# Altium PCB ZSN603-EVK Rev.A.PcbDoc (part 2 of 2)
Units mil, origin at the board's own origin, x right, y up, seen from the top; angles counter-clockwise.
Board outline 3937.01 x 3149.67 mil, 2 copper layers (Top Layer, Bottom Layer); 139 components, 76 nets, 380 pads, 360 vias.
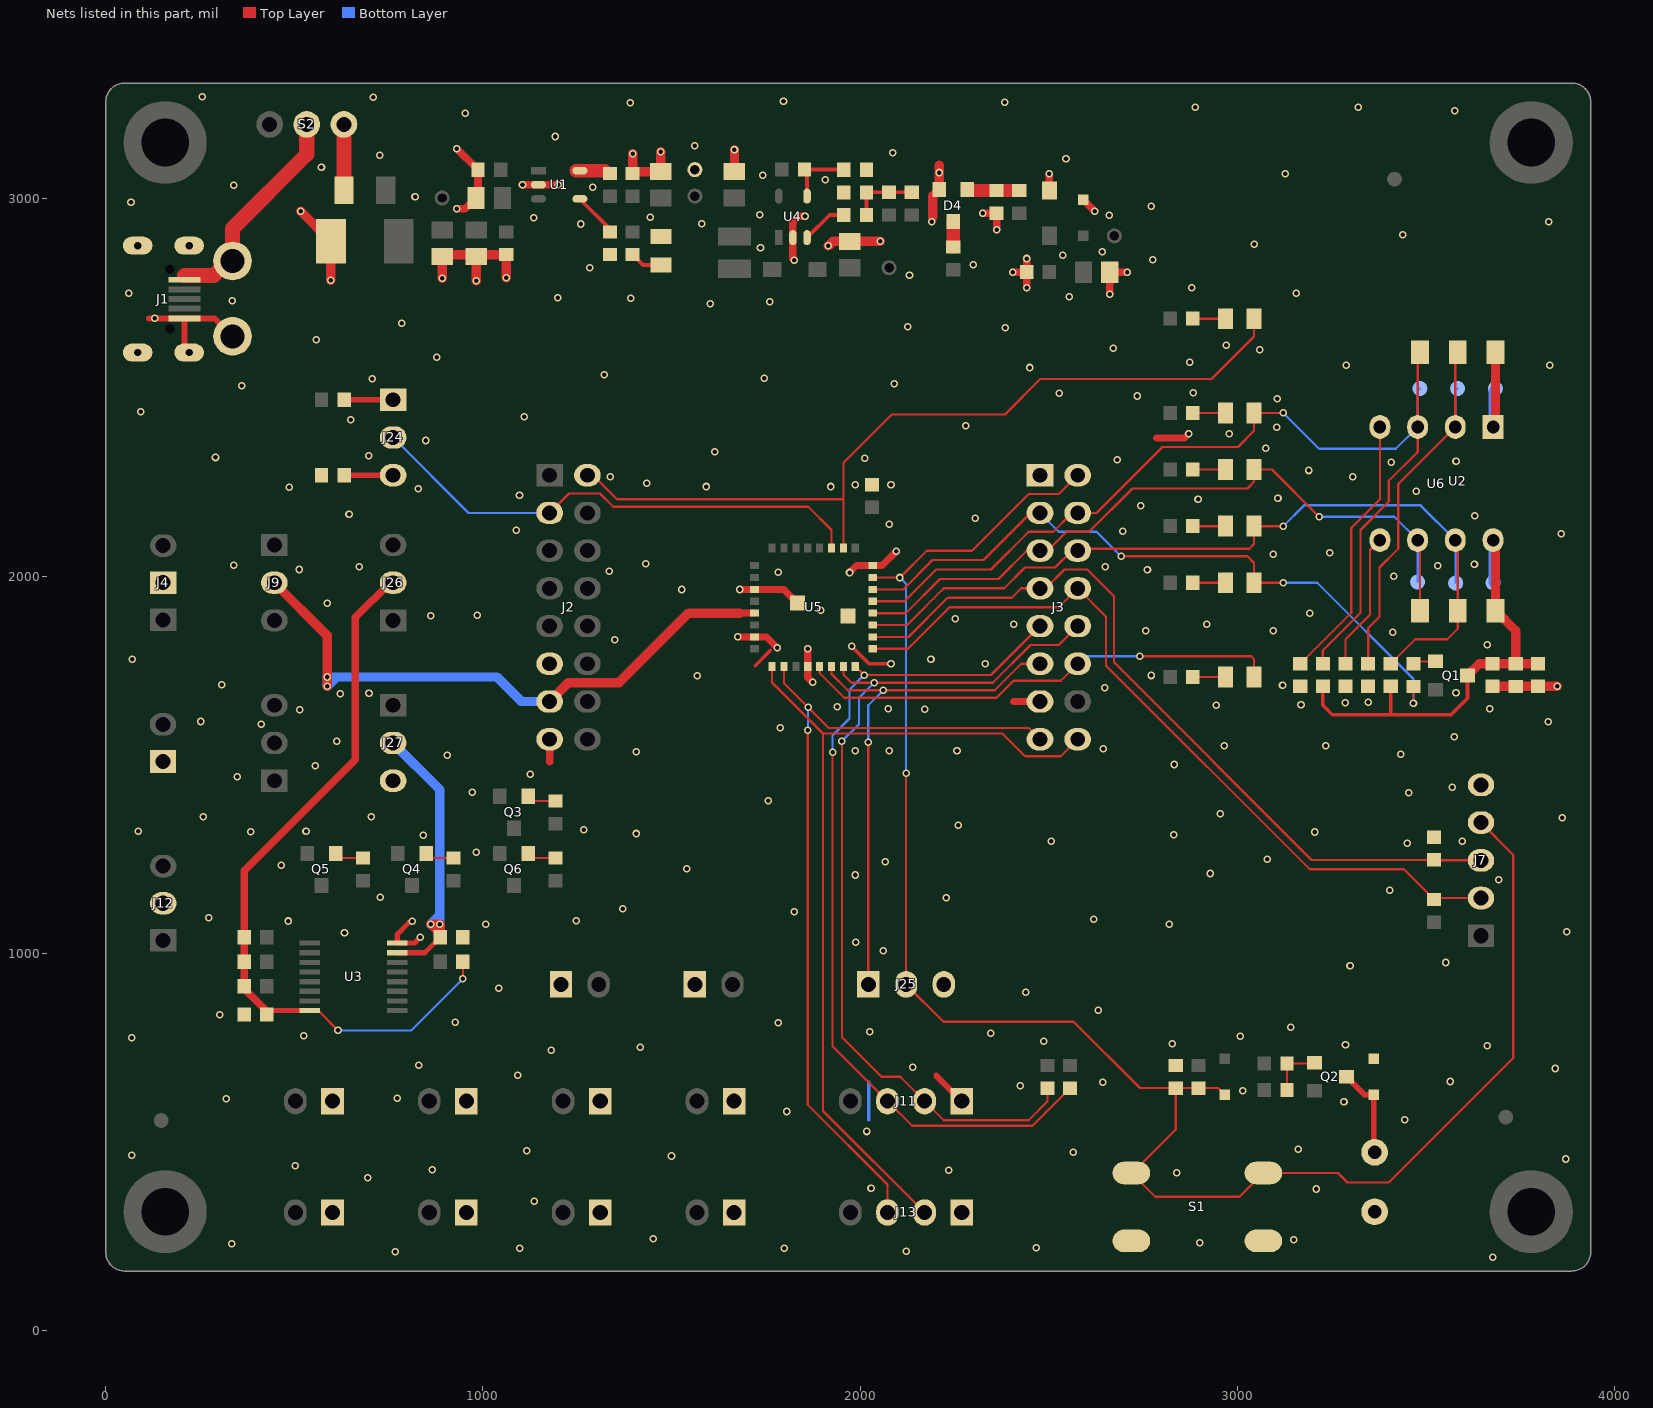
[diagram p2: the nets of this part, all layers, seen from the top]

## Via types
v1: diameter 20, hole 12, Top Layer to Bottom Layer, tented both sides, 360 vias

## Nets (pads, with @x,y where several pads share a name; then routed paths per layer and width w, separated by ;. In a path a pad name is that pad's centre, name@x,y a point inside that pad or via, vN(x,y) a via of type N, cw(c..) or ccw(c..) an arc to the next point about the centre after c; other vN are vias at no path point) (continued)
GND: BZ1.2 C1.2 C2.2 C3.2 C4.2 C5.2 C6.2 C7.2 C8.2 C9.2 C11.2 C12.2 C14.2 C15.1 C16.2 C17.2 C18.2 C19.2 C36.2 D2.1 D4.2 D5.2 D6.1 D7.2 J1.5 J1.6 J1.7 J1.8 J1.9 J2.11 J2.15 J3.1 J3.13 J4.2 J5.1 J6.1 J7.5 J10.1 J11.1 J12.2 J13.1 J14.1 J15.1 J16.1 J17.1 J18.1 J19.1 J20.1 J21.1 J22.1 J23.2 J25.3 J27.3 LED1.2 R5.1 R8.2 R24.1 R25.1 R27.1 R30.1 R31.1 R32.1 R38.1 S1.2 S1.3 T3.1 T5.1 U1.2 U2.6 U3.8 U4.2 U5.4 U5.16 U5.27 U5.31 U5.33 U5.34 U6.1 | length 4007.3
  Top Layer w10: 1721.97,1762.48 1761.97,1802.48 ; v1(1977.97,1813.48) 2023.97,1767.48 v1(2081.97,1767.48)
  Top Layer w13.78: 803.47,1080.98 773.11,1050.62 U3.8@773.11,1027.05 818.54,1027.05 v1(833.97,1042.48)
  Top Layer w15.75: 115.09,2683.36 J1.5@209.02,2683.36 ; J1.7@221.22,2592.81 209.02,2605.02 J1.5@209.02,2683.36 ; J23.2@336.16,2635.54 288.34,2683.36 J1.5@209.02,2683.36 ; 2201.97,675.43 J11.1@2269.61,607.8
  Top Layer w19: v1(1676.23,1838.74) U5.31@1720.28,1838.74 1751.71,1838.74 v1(1780.97,1809.48) ; v1(1680.97,1964.48) 1681.22,1964.72 U5.27@1720.28,1964.72 1797.45,1964.72 U5.33@1833.67,1928.5 ; v1(1861.23,1807.73) U5.4@1861.23,1760.79 1861.23,1731.23 v1(1873.97,1718.48) ; v1(1971.97,2009.48) 1990.21,2027.72 U5.16@2033.67,2027.72 2058.21,2027.72 v1(2095.97,2065.48) ; 2406.97,1667.48 J3.13@2476.97,1667.48 ; 2786.47,2366.48 2859.97,2366.48 v1(2870.97,2377.48)
  Top Layer w20: v1(930.97,2973.48) 952.97,2973.48 C1.2@981.97,3002.48 986.97,3007.48 C2.2@986.97,3077.48 v1(930.97,3133.48) ; v1(1104.97,3037.48) U1.2@1146.97,3037.48 v1(1199.97,3037.48) ; 1176.97,1507.48 J2.15@1176.97,1567.48 ; v1(1825.97,2837.48) 1821.97,2841.48 U4.2@1821.97,2897.48 1821.97,2937.48 1837.97,2953.48 v1(1853.97,2953.48) ; v1(2325.48,2962.48) C15.1@2361.97,2962.48 v1(2361.97,2917.97) ; v1(2405,2806) R27.1@2442,2806 ; v1(2442,2765) R27.1@2442,2806 ; v1(2442,2842) R27.1@2442,2806 ; D5.2@2501.97,3022.48 v1(2501.97,3066.97) ; D7.2@2591.97,2997.48 v1(2621.97,2967.48) ; v1(2662,2747) C14.2@2662,2806 v1(2708,2806)
  Top Layer w25: v1(516.97,2967.48) D6.1@596.97,2887.48 v1(596.97,2784.48) ; v1(891.97,2789.48) C16.2@891.97,2847.48 896.97,2852.48 C18.2@1061.97,2852.48 v1(1061.97,2791.48) ; v1(981.97,2782.48) C17.2@981.97,2847.48 ; v1(1396.97,3119.48) C5.2@1396.97,3067.48 1401.97,3072.48 C4.2@1471.97,3072.48 v1(1471.97,3125.48) ; C12.2@1666.97,3072.48 v1(1666.97,3130.48) ; v1(1915.97,2875.48) 1927.97,2887.48 C11.2@1971.97,2887.48 v1(2053.97,2887.48) ; 2192.97,2951.48 2192.97,3008.38 D4.2@2209.57,3024.98 2209.57,3089.08 ; R8.2@3676.97,1707.48 C36.2@3796.97,1707.48 v1(3847.97,1707.48) ; U6.1@3678.24,2395.4 3684.78,2401.94 U2.6@3684.78,2593.45
  Bottom Layer w10: 2023.07,558.58 2023.07,657.48
  Bottom Layer w25: U6.1@3678.24,2395.4 3678.24,2491.4 T5.1@3684.24,2497.4
  other v1: 3677,194 766.97,208.48 2122.97,209.48 1097.97,217.48 1798.97,217.48 2466.97,219.48 333.97,229.48 2899.97,232.48 3150,240 1451.97,242.48 1135.97,342.48 3210,375 2028.97,377.48 694.97,404.48 2838.97,417.48 2234.97,424.48 865.97,426.48 502.97,436.48 3870.97,454.48 1499.97,462.48 68.97,464.48 2564.97,472.48 1115.97,476.48 3161.97,480.48 2017.97,527.48 3443.97,558.48 1804.97,580.48 3282.97,606.48 318.97,614.48 772.97,615.48 3015,635 2424.97,648.48 2642.97,658.48 3565,660 1091.97,676.48 3842.97,694.48 2139.97,697.48 829.97,703.48 1180.97,742.48 1416.97,750.48 3662.97,754.48 3286.97,757.48 2827.97,760.48 2486.97,766.48 68.97,776.48 3007.97,779.48 524.97,781.48 2346.97,788.48 2025.97,792.48 3141.97,803.48 1782.97,815.48 926.97,816.48 301.97,836.48 2631.97,849.48 2438.97,896.48 1041.97,907.48 3298.97,966.48 3552.97,975.48 2061.97,1006.48 1987.97,1029.48 632.97,1054.48 3873.97,1056.48 1006.97,1077.48 2819.97,1077.48 812.97,1084.48 483.97,1085.48 1246.97,1086.48 2620,1090 272.97,1094.48 1825.97,1109.48 1370.97,1118.48 2228.97,1147.48 727.97,1148.48 3403.97,1167.48 3692.97,1194.48 1986.97,1207.48 2927.97,1211.48 1540.97,1224.48 464.97,1233.48 2066.97,1242.48 3079.97,1249.48 981.97,1267.48 3450.97,1291.48 2506.97,1297.48 3595.97,1297.48 841.97,1312.48 2831.97,1314.48 1406.97,1317.48 3205.97,1321.48 383.97,1322.48 85.97,1323.48 530.97,1323.48 1266.97,1327.48 2260,1340 3861.97,1359.48 257.97,1361.48 703.97,1361.48 2955,1370 1756.97,1404.48 3455,1425 971.97,1427.48 3570,1440 348.97,1467.48 1125,1475 555.97,1497.48 2832.97,1500.48 905.97,1524.48 3433.97,1527.48 1406.97,1534.48 1986.97,1537.48 2076.97,1537.48 2256.97,1537.48 2644.97,1542.48 2965,1550 3235,1550 611.97,1562.48 3574.97,1574.48 1787.97,1598.48 411.97,1607.48 3824.97,1613.48 251.97,1614.48 513.97,1645.48 2171.97,1647.48 2074.97,1648.48 3668.97,1648.48 1939.97,1653.48 2943.97,1657.48 3168.97,1658.48 3285.97,1664.48 3346.97,1665.48 621.97,1687.48 697.97,1689.48 3579.97,1690.48 2648.97,1703.48 3120,1710 306.97,1712.48 1567.97,1735.48 2771.97,1736.48 2331.97,1767.48 69.97,1779.48 2187.97,1779.48 3662.97,1818.48 1349.97,1831.48 3411.97,1851.48 2757.97,1855.48 3095,1855 2406.97,1872.48 2918.97,1872.48 2251.97,1887.48 861.97,1894.48 984.97,1896.48 3191.97,1901.48 1895.97,1909.48 586.97,1927.48 1526.97,1964.48 3414.97,1999.48 1782.97,2010.48 1334.97,2012.48 2761.97,2016.48 512.97,2017.48 671.97,2024.48 2649.97,2024.48 3530.97,2027.48 339.97,2028.48 3628.97,2031.48 1431.97,2032.48 3094.97,2058.48 3244.97,2062.48 3858.97,2112.48 2696.97,2119.48 1088.97,2121.48 2076.97,2137.48 2304.97,2153.48 3630,2160 644.97,2163.48 2743.97,2186.48 2895.97,2203.48 3107.97,2206.48 1096.97,2214.48 3475,2225 827.97,2231.48 485.97,2235.48 1591.97,2237.48 1921.97,2237.48 1986.97,2242.48 2081.97,2242.48 1434.97,2246.48 1337.97,2263.48 3305.97,2263.48 3190,2280 3407.97,2301.48 3580,2305 2681.97,2308.48 2011.97,2312.48 290.97,2314.48 696.97,2318.48 1614.97,2329.48 3074.97,2338.48 848.97,2359.48 2978.97,2377.48 3105,2395 2279.97,2398.48 649.97,2414.48 1109.97,2422.48 92.97,2435.48 3105.97,2470.48 2734.97,2477.48 2527.97,2484.48 2882.97,2486.48 360,2505 2089.97,2510.48 706.97,2523.48 1745.97,2524.48 1321.97,2533.48 2450,2553 3288.97,2558.48 3827.97,2558.48 2873.97,2566.48 877.97,2580.48 3060,2600 2670.97,2604.48 2970.97,2612.48 557.97,2626.48 2385,2659 2126.97,2661.48 785,2670 130,2683.36 1602.97,2722.48 1760.97,2727.48 335,2730 1391.97,2736.48 1198.97,2738.48 2555,2741 60.97,2750.48 3156.97,2750.48 2879,2764 2131,2798 1282.97,2817.48 2300,2825 2776,2839 2537,2851 2642,2860 1735.97,2870.48 3045,2880 3438.97,2904.48 1258.97,2933.48 1579.97,2934.48 3825.97,2939.48 2190,2940 1134.97,2950.48 1443.97,2951.48 2661,2957 1733.97,2958.48 2771.97,2980.48 66.97,2991.48 819.97,3005.48 1290.97,3030.48 338.97,3036.48 1907.97,3050.48 1741.97,3062.48 3126.97,3066.48 2209.57,3070 571.97,3084.48 2545.97,3106.48 725.97,3115.48 2086.97,3122.48 1561.97,3141.48 1191.97,3165.48 952.97,3227.48 3576.97,3233.48 2888.97,3242.48 3320.97,3242.48 1390.97,3254.48 2382.97,3256.48 1796.97,3258.48 708.97,3269.48 255.97,3270.48
NetBZ1_1: BZ1.1 D2.2 Q2.3 | length 246
  Top Layer w15: Q2.3@3289.47,672.48 3336.97,624.98 D2.2@3361.97,624.98 3361.97,474.4 BZ1.1@3364.24,472.14
NetC3_1: C3.1 U1.4 | length 120.7
  Top Layer w10: U1.4@1256.97,3000.08 1336.97,2920.08 C3.1@1336.97,2912.48
NetC10_2: C10.2 R21.1 R23.1 R25.2 | length 180
  Top Layer w10: R23.1@2016.97,2957.48 R25.2@2016.97,3017.48 R21.1@2076.97,3017.48 C10.2@2136.97,3017.48
NetC13_2: C13.2 D4.3 | length 67.5
  Top Layer w35: C13.2@2246.97,2872.48 D4.3@2246.97,2939.98
NetC15_2: C15.2 D4.1 R26.1 | length 138.6
  Top Layer w35: D4.1@2284.37,3024.98 2286.87,3022.48 C15.2@2361.97,3022.48 R26.1@2421.97,3022.48
NetF1_1: F1.1 S2.3 | length 170.3
  Top Layer w40: S2.3@631.39,3197.54 631.39,3027.94 F1.1@631.85,3027.48
NetJ1_1: J1.1 J23.1 S2.2 | length 587.1
  Top Layer w40: 208.32,2797.48 286.97,2797.48 325.04,2835.54 J23.1@336.16,2835.54 336.16,2921.67 532.96,3118.47 S2.2@532.96,3197.54
NetJ24_1: J24.1 R37.2 | length 130
  Top Layer w15: R37.2@631.97,2467.48 J24.1@761.97,2467.48
NetJ24_3: J24.3 R38.2 | length 130
  Top Layer w15: R38.2@631.97,2267.48 J24.3@761.97,2267.48
NetLED1_1: LED1.1 R2.2 | length 86.5
  Top Layer w10: R2.2@1396.97,2852.48 1424.65,2824.8 LED1.1@1471.97,2824.8
NetLED2_1: LED2.1 R12.2 | length 87.3
  Top Layer w6: R12.2@2881.97,1732.48 LED2.1@2969.3,1732.48
NetLED3_1: LED3.1 R33.1 | length 87.3
  Top Layer w6: R33.1@2881.97,1982.48 LED3.1@2969.3,1982.48
NetLED4_1: LED4.1 R34.1 | length 87.3
  Top Layer w6: R34.1@2881.97,2132.48 LED4.1@2969.3,2132.48
NetLED5_1: LED5.1 R35.1 | length 87.3
  Top Layer w6: R35.1@2881.97,2432.48 LED5.1@2969.3,2432.48
NetLED6_1: LED6.1 R36.1 | length 87.3
  Top Layer w6: R36.1@2881.97,2282.48 LED6.1@2969.3,2282.48
NetLED7_1: LED7.1 R39.1 | length 87.3
  Top Layer w6: R39.1@2881.97,2682.48 LED7.1@2969.3,2682.48
NetQ1_1: Q1.1 R9.2 | length 61.2
  Top Layer w6: R9.2@3467.24,1767.4 3473.64,1773.8 Q1.1@3525.74,1773.8
NetQ2_1: Q2.1 R10.1 R11.2 | length 143.5
  Top Layer w6: R10.1@3131.97,637.48 R11.2@3131.97,707.48 3202.07,707.48 Q2.1@3204.47,709.88
NetQ3_1: Q3.1 R15.1 | length 77.8
  Top Layer w6: Q3.1@1119.73,1416.33 1132.23,1403.83 R15.1@1192.33,1403.83
NetQ4_1: Q4.1 R16.1 | length 77.8
  Top Layer w6: Q4.1@849.37,1264.98 861.87,1252.48 R16.1@921.97,1252.48
NetQ5_1: Q5.1 R19.1 | length 77.8
  Top Layer w6: Q5.1@609.37,1264.98 621.87,1252.48 R19.1@681.97,1252.48
NetQ6_1: Q6.1 R20.1 | length 77.8
  Top Layer w6: Q6.1@1119.73,1264.98 1132.23,1252.48 R20.1@1192.33,1252.48
NetR1_1: R1.1 U1.5 | length 93.1
  Top Layer w35: U1.5@1246.97,3074.88 U1.5@1256.97,3074.88 1322.57,3074.88 1329.97,3067.48 R1.1@1336.97,3067.48
NetR22_1: R22.1 R24.2 U4.4 | length 178.1
  Top Layer w10: U4.4@1859.37,3007.48 1859.37,3071.04 R22.1@1852.44,3077.98 1956.48,3077.98 R24.2@1956.97,3077.48
NetR23_2: R23.2 U4.3 | length 122.5
  Top Layer w10: U4.3@1859.37,2897.48 1919.37,2957.48 R23.2@1956.97,2957.48
NetR30_2: R30.2 U6.4 | length 715.4
  Top Layer w6: R30.2@3166.97,1767.48 3301.97,1902.48 3301.97,2127.48 3378.24,2203.75 U6.4@3378.24,2395.4
NetR31_2: R31.2 U6.5 | length 365.7
  Top Layer w6: R31.2@3286.97,1767.48 3286.97,1832.48 3351.97,1897.48 3351.97,2069.13 U6.5@3378.24,2095.4
NRST: C6.1 D1.1 J3.2 J7.4 J25.2 R4.1 S1.1 S1.4 U5.15 | length 4854.1
  Top Layer w6: U5.15@2033.67,1996.22 v1(2105.71,1996.22) 2176.97,2067.48 2296.97,2067.48 2446.97,2217.48 2526.97,2217.48 J3.2@2576.97,2267.48 ; v1(2121.97,1477.48) J25.2@2121.97,917.48 2220.97,818.48 2565.97,818.48 2741.97,642.48 C6.1@2836.97,642.48 ; D1.1@2966.97,624.98 2949.47,642.48 R4.1@2896.97,642.48 C6.1@2836.97,642.48 ; J7.4@3646.24,1346.4 3731.97,1260.66 3731.97,722.48 3401.97,392.48 3291.97,392.48 3267.06,417.4 S1.4@3069.24,417.4 3006.18,354.33 2782.3,354.33 S1.1@2719.24,417.4 2721.89,417.4 2836.97,532.48 C6.1@2836.97,642.48
  Bottom Layer w6: v1(2105.71,1996.22) 2121.97,1979.96 v1(2121.97,1477.48)
PA2/NC: J2.2 LED7.2 U5.18 | length 2206.1
  Top Layer w6: J2.2@1276.97,2267.48 1291.97,2267.48 1355.62,2203.83 1955.71,2203.83 ; U5.18@1955.71,2074.17 1955.71,2203.83 ; LED7.2@3044.65,2682.48 3044.65,2635.16 2931.97,2522.48 2477.97,2522.48 2383.97,2428.48 2083.97,2428.48 1955.71,2300.22 1955.71,2203.83
PA3/MODE_DET: J2.3 J24.2 U5.19 | length 1354.3
  Top Layer w6: J2.3@1176.97,2167.48 1228.33,2218.83 1310.62,2218.83 1345.62,2183.83 1862.33,2183.83 1924.22,2121.94 U5.19@1924.22,2074.17
  Bottom Layer w6: J24.2@761.97,2367.48 961.97,2167.48 J2.3@1176.97,2167.48
PA9/UART1_TX: J3.15 J13.3 U5.2 | length 2212.8
  Top Layer w6: U5.2@1798.23,1760.79 1798.23,1716.22 v1(1861.97,1652.48) 1916.97,1597.48 2446.97,1597.48 J3.15@2476.97,1567.48 ; v1(1860.93,1591.44) 1860.93,598.52 2072.76,386.69 J13.3@2072.76,312.8
  Bottom Layer w6: v1(1860.93,1591.44) 1861.97,1592.48 v1(1861.97,1652.48)
PA10/UART1_RX: J3.16 J13.2 U5.1 | length 2334
  Top Layer w6: U5.1@1766.74,1760.79 1766.74,1717.72 1901.97,1582.48 ; J13.2@2171.18,312.8 1901.97,582.01 1901.97,1582.48 ; J3.16@2576.97,1567.48 2531.97,1522.48 2436.97,1522.48 2376.97,1582.48 1901.97,1582.48
PA12/LED: J3.12 LED2.2 U5.5 | length 1293.1
  Top Layer w6: U5.5@1892.72,1760.79 1892.72,1742.73 1957.97,1677.48 2361.97,1677.48 2406.97,1722.48 2531.97,1722.48 J3.12@2576.97,1767.48 ; v1(2741.97,1787.48) 3036.97,1787.48 3044.65,1779.8 LED2.2@3044.65,1732.48
  Bottom Layer w6: J3.12@2576.97,1767.48 2596.97,1787.48 v1(2741.97,1787.48)
PA13/SWDIO/BOOT0: J3.8 J7.2 R3.1 U5.9 | length 2098.4
  Top Layer w6: U5.9@2033.67,1807.24 2126.74,1807.24 2236.97,1917.48 2526.97,1917.48 J3.8@2576.97,1967.48 2651.97,1892.48 2651.97,1762.48 3191.97,1222.48 3441.97,1222.48 R3.1@3521.97,1142.48 3525.89,1146.4 J7.2@3646.24,1146.4
PA14/SWCLK/BOOT1: J3.7 J7.3 R5.2 U5.10 | length 2108.5
  Top Layer w6: U5.10@2033.67,1838.74 2128.23,1838.74 2231.97,1942.48 2401.97,1942.48 2426.97,1967.48 J3.7@2476.97,1967.48 2491.97,1967.48 2541.97,2017.48 2601.97,2017.48 2673.19,1946.27 2673.19,1771.27 3196.97,1247.48 R5.2@3521.97,1247.48 3523.06,1246.4 J7.3@3646.24,1246.4
PA15/INT: J3.11 J25.1 U5.6 | length 1416.6
  Top Layer w6: U5.6@1924.22,1760.79 1924.22,1740.24 1966.97,1697.48 v1(2061.97,1697.48) 2356.97,1697.48 2426.97,1767.48 J3.11@2476.97,1767.48 ; J25.1@2021.97,917.48 v1(2021.97,1559.98)
  Bottom Layer w6: v1(2021.97,1559.98) 2021.97,1657.48 v1(2061.97,1697.48)
PB3/SAM_RST: J3.6 LED4.2 R28.1 T6.1 U2.2 U5.11 U6.7 | length 2310.3
  Top Layer w6: U5.11@2033.67,1870.24 2124.73,1870.24 2221.97,1967.48 2381.97,1967.48 2436.97,2022.48 2516.97,2022.48 2561.97,2067.48 J3.6@2576.97,2067.48 2581.97,2072.48 3031.97,2072.48 3044.65,2085.16 LED4.2@3044.65,2132.48 v1(3121.97,2132.48) ; R28.1@3406.97,1767.48 3471.97,1832.48 3556.97,1832.48 3584.78,1860.29 U2.2@3584.78,1908.41 3584.78,2088.85 U6.7@3578.24,2095.4
  Bottom Layer w6: v1(3121.97,2132.48) 3176.97,2187.48 3486.16,2187.48 U6.7@3578.24,2095.4 3579.24,2094.4 T6.1@3579.24,1981.4
PB4/SAM_CLK: J3.5 LED6.2 T7.1 U2.3 U5.12 U6.6 | length 1999.4
  Top Layer w6: U5.12@2033.67,1901.73 2121.22,1901.73 2211.97,1992.48 2366.97,1992.48 2441.97,2067.48 J3.5@2476.97,2067.48 2496.97,2067.48 2546.97,2117.48 2606.97,2117.48 2721.97,2232.48 3026.97,2232.48 3044.65,2250.16 LED6.2@3044.65,2282.48 3091.97,2282.48 v1(3216.97,2157.48) ; U6.6@3478.24,2095.4 3484.78,2088.85 U2.3@3484.78,1908.41
  Bottom Layer w6: v1(3216.97,2157.48) 3416.16,2157.48 U6.6@3478.24,2095.4 T7.1@3478.24,1984.4
PB5/SAM_IO: J3.4 LED5.2 R29.1 T8.1 U2.4 U5.13 U6.3 | length 2779.7
  Top Layer w6: U5.13@2033.67,1933.23 2117.72,1933.23 2201.97,2017.48 2346.97,2017.48 2446.97,2117.48 2511.97,2117.48 2561.97,2167.48 J3.4@2576.97,2167.48 2626.97,2167.48 2801.97,2342.48 3001.97,2342.48 3044.65,2385.16 LED5.2@3044.65,2432.48 v1(3121.97,2432.48) ; R29.1@3226.97,1767.48 3226.97,1802.48 3326.97,1902.48 3326.97,2122.48 3401.97,2197.48 3401.97,2252.48 3478.24,2328.75 U6.3@3478.24,2395.4 3478.24,2586.91 U2.4@3484.78,2593.45
  Bottom Layer w6: v1(3121.97,2432.48) 3216.97,2337.48 3420.33,2337.48 U6.3@3478.24,2395.4 3478.24,2491.4 T8.1@3484.24,2497.4
PB6/I2C_SCL: J3.9 J11.3 R7.1 U5.8 | length 2330.6
  Top Layer w6: v1(1926.97,1532.48) 1926.97,753.58 J11.3@2072.76,607.8 2138.07,542.48 2456.97,542.48 R7.1@2556.97,642.48 ; U5.8@1987.21,1760.79 v1(2010.52,1737.48) 2346.97,1737.48 J3.9@2476.97,1867.48
  Bottom Layer w6: v1(1926.97,1532.48) 1926.97,1577.48 1971.97,1622.48 1971.97,1698.94 v1(2010.52,1737.48)
PB7/I2C_SDA: J3.10 J11.2 R6.1 U5.7 | length 2381.3
  Top Layer w6: v1(1951.97,1562.48) 1951.97,777.48 2056.97,672.48 2106.5,672.48 J11.2@2171.18,607.8 2221.5,557.48 2446.97,557.48 2496.97,607.48 R6.1@2496.97,642.48 ; U5.7@1955.71,1760.79 1955.71,1738.74 1976.97,1717.48 v1(2036.97,1717.48) 2351.97,1717.48 2451.97,1817.48 2526.97,1817.48 J3.10@2576.97,1867.48
  Bottom Layer w6: v1(1951.97,1562.48) 1996.97,1607.48 1996.97,1677.48 v1(2036.97,1717.48)
PB8/SAM_NPWR: J3.3 LED3.2 R9.1 U5.14 | length 1839.7
  Top Layer w6: U5.14@2033.67,1964.72 2114.22,1964.72 2191.97,2042.48 2326.97,2042.48 2451.97,2167.48 J3.3@2476.97,2167.48 ; v1(2691.97,2052.48) 3026.97,2052.48 3044.65,2034.8 LED3.2@3044.65,1982.48 v1(3121.97,1982.48) ; v1(3467.24,1662.75) R9.1@3467.24,1707.4
  Bottom Layer w6: J3.3@2476.97,2167.48 2526.97,2117.48 2626.97,2117.48 v1(2691.97,2052.48) ; v1(3121.97,1982.48) 3211.97,1982.48 3467.24,1727.21 v1(3467.24,1662.75)
PVPP: R32.2 T11.1 U2.5 U6.2 | length 1029
  Top Layer w6: R32.2@3346.97,1767.48 3346.97,1862.48 3376.97,1892.48 3376.97,2022.48 3426.97,2072.48 3426.97,2244.13 U6.2@3578.24,2395.4 3578.24,2586.91 U2.5@3584.78,2593.45
  Bottom Layer w6: U6.2@3578.24,2395.4 3578.24,2491.4 T11.1@3584.24,2497.4
SAM_VCC: C7.1 C36.1 Q1.3 R8.1 R28.2 R29.2 T4.1 U2.1 U6.8 | length 1262.4
  Top Layer w10: R29.2@3226.97,1707.48 3226.97,1657.48 3251.97,1632.48 3406.97,1632.48 ; R28.2@3406.97,1707.48 3406.97,1632.48 ; Q1.3@3610.74,1736.4 3610.74,1676.25 3566.97,1632.48 3406.97,1632.48
  Top Layer w25: Q1.3@3610.74,1736.4 3641.83,1767.48 R8.1@3676.97,1767.48 C7.1@3738.24,1767.48 ; U6.8@3678.24,2095.4 3684.78,2088.85 U2.1@3684.78,1908.41 3738.24,1854.95 C7.1@3738.24,1767.48 ; C7.1@3738.24,1767.4 C7.1@3738.24,1767.48 ; C36.1@3796.97,1767.48 C7.1@3738.24,1767.48
  Bottom Layer w25: T4.1@3678.24,1982.4 U6.8@3678.24,2095.4
VCC_4051: C9.1 J26.2 R13.2 R14.2 R17.2 R18.2 U3.16 | length 1973.7
  Top Layer w6: U3.16@540.83,847.91 563.3,847.91 v1(615.74,795.48) ; v1(946.97,932.48) R18.2@946.97,977.48
  Top Layer w13.78: C9.1@432.97,847.91 U3.16@540.83,847.91
  Top Layer w20: C9.1@425.97,847.48 366.97,906.48 R14.2@366.97,912.48 R13.2@366.97,977.48 R17.2@366.97,1042.48 366.97,1218.48 661.97,1513.48 661.97,1890.48 753.97,1982.48 J26.2@761.97,1982.48 ; C9.1@426.97,837.48 C9.1@432.97,831.48
  Bottom Layer w6: v1(615.74,795.48) 809.97,795.48 v1(946.97,932.48)
VCC_ANT: J2.13 J9.2 U5.29 | length 1650.6
  Top Layer w19: 1681.22,1901.73 U5.29@1720.28,1901.73
  Top Layer w25: J9.2@446.97,1982.48 586.97,1842.48 v1(586.97,1732.48) v1(586.97,1707.48) ; J2.13@1176.97,1667.48 1226.97,1717.48 1360.97,1717.48 1545.23,1901.73 1681.22,1901.73
  Bottom Layer w25: J2.13@1176.97,1667.48 1101.97,1667.48 1036.97,1732.48 611.97,1732.48 ; 611.97,1732.48 v1(586.97,1732.48) v1(586.97,1707.48) 611.97,1732.48
VEE_4051: C8.1 J27.2 U3.7 | length 814.9
  Top Layer w13.78: U3.7@773.11,1001.46 845.95,1001.46 C8.1@886.97,1042.48
  Top Layer w25: C8.1@886.97,1042.48 C8.1@886.97,1052.48 ; C8.1@886.97,1052.48 886.97,1076.48 v1(885.97,1077.48) v1(861.97,1077.48) C8.1@886.97,1052.48
  Bottom Layer w25: J27.2@761.97,1557.48 885.97,1433.48 885.97,1101.48 ; 885.97,1101.48 v1(885.97,1077.48) v1(861.97,1077.48) 885.97,1101.48
pads on no net: HOLE1.1 HOLE2.1 HOLE3.1 HOLE4.1 J1.0 J1.2 J1.3 J1.4 MARK2.0 MARK3.0 MARK4.0 S2.1

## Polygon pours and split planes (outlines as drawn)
GND on Top Layer "GND_L01_P1002" (solid, remove dead copper, pour order 1002): -2.36,179.98 ccw(c47.64,179.98) 47.2,129.99 3884.61,129.99 3884.61,129.92 ccw(c3884.61,179.92) 3934.61,179.49 3934.61,3229.98 ccw(c3885.1,3229.98) 3885.53,3279.48 3885.53,3279.59 47.21,3279.59 47.6,3279.55 ccw(c47.6,3229.55) -2.4,3229.99
GND on Bottom Layer "GND_L02_P1003" (solid, remove dead copper, pour order 1003): 0,207.54 ccw(c50,207.54) 49.56,157.54 3886.97,157.54 3886.97,157.48 ccw(c3886.97,207.48) 3936.97,207.04 3936.97,3257.54 ccw(c3887.46,3257.54) 3887.89,3307.04 3887.89,3307.15 49.57,3307.15 49.96,3307.11 ccw(c49.96,3257.11) -0.04,3257.54

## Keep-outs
Keep-Out Layer:
  lines w5: -0.07,3257.45 cw(c49.57,3257.45) 49.14,3307.08 ; -0.04,207.04 -0.04,3257.45 ; 0,-65.55 0,0 ; 0,207.54 ccw(c50,207.54) 49.56,157.54 ; 49.46,157.54 3886.97,157.54 ; 49.57,3307.09 3887.89,3307.09 ; 3886.97,157.48 ccw(c3886.97,207.48) 3936.97,207.04 3936.97,3257.54 ccw(c3887.46,3257.54) 3887.89,3307.04 ; 3936.97,-65.55 3936.97,0 4002.52,0 ; 3936.97,3307.09 4002.52,3307.09

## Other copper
Top Layer:
  pour cut-out: 782.68,3073.9 638.39,3073.9 622.97,3058.48 622.97,3038.48 657.97,3003.48 750.26,3003.48 782.68,2971.06
  pour cut-out: 1773.93,2974.82 1855,2974.82 1855,2985 1773.93,2985
  pour cut-out: 3546.16,2639.95 3546.16,2625 3505,2625 3505,2639.95
  pour cut-out: 1178.75,1670 1278.75,1670 1278.75,1570 1171.25,1570

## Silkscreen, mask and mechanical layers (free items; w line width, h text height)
Top Overlay:
  region: 1908.57,106.48 1908.57,94.48 1763.57,94.48 1763.57,67.48 1908.57,67.48 1908.57,56.48 1970.57,81.48
  lines w7.87: 991.15,1627.48 991.15,1130.08 ; 991.15,1697.31 991.15,1836.48 ; 991.15,1907.48 991.15,2704.88 2762.8,2704.88 2762.8,2207.48 ; 1365.16,1497.48 1365.16,1228.5 2388.78,1228.5 2388.78,1497.48 ; 1365.16,2347.48 1365.16,2606.46 2388.78,2606.46 2388.78,2362.48 ; 1546.15,1228.5 1546.15,1350.08 1591.15,1395.08 2162.8,1395.08 2207.8,1350.08 2207.8,1228.5 ; 2762.8,1522.48 2762.8,1130.08 ; 2762.8,1617.48 2762.8,1932.48 ; 991.15,1130.08 2762.8,1130.08 ; 991.15,1130.08 2762.8,1130.08
  lines w8: 1763.57,67.48 1763.57,94.48 1908.57,94.48 1908.57,106.48 1970.57,81.48 1908.57,56.48 1908.57,67.48 1763.57,67.48
  text "ZSN603-EVK" at 2881.97,3156.48 h80
  text "OFF" at 369.96,3087.54 h65
  text "ON" at 579.96,3087.54 h65
  text "190808 Rev.A" at 2916.97,3081.48 h60
  text "P/N:13.01.04461" at 2891.97,3006.48 h60
  text "SAM" at 3726,2754 h65
  text "PWR" at 1403.97,2723.48 h65
  text "SDATA" at 2928.97,2486.48 h36
  text "POWER" at 49.96,2452.54 h65
  text "3V3" at 839.11,2448.54 h30
  text "MODE_DET" at 481.97,2352.48 h30
  text "SCLK" at 2948.97,2333.48 h36
  text "3.3V" at 1021.97,2252.48 h30
  text "NC" at 1355.15,2252.48 h30
  text "GND" at 2325.38,2252.48 h30
  text "NRST" at 2641.97,2252.48 h30
  text "GND" at 835.96,2250.54 h30
  text "SRST" at 2949.97,2184.48 h36
  text "SAM_nP" at 2243.68,2156.05 h30
  text "M_D" at 1029.54,2152.48 h30
  text "SAM_IO" at 2641.97,2152.48 h30
  text "SCH1" at 1355.15,2151.05 h30
  text "5V" at 831.97,2072.48 h30
  text "5V_ANT" at 510.97,2069.54 h30
  text "TX1" at 330.97,2054.48 h30 r90
  text "SAM_CLK" at 2216.97,2054.62 h30
  text "SCH2" at 1007.83,2052.48 h30
  text "SAM_RST" at 2641.97,2052.48 h30
  text "SCH3" at 1355.15,2049.62 h30
  text "SPWR" at 2943.97,2034.48 h36
  text "VCC_ANT" at 510.97,1968.48 h30
  text "VCC_S" at 826.97,1967.48 h30
  text "SEN" at 1037.4,1952.48 h30
  text "BOOT0" at 2646.97,1952.48 h30
  text "3.3V" at 1355.15,1948.2 h30
  text "BOOT1" at 2284.82,1948.2 h30
  text "GND" at 330.97,1943.48 h30 r90
  text "3V3_ANT" at 510.97,1867.54 h30
  text "8V" at 831.97,1867.48 h30
  text "SDA" at 2646.97,1857.48 h30
  text "RX" at 330.97,1856.48 h30 r90
  text "CZ_TX1" at 1355.15,1856.76 h30
  text "CZ_RX" at 977.7,1852.48 h30
  text "SCL" at 2328.23,1846.77 h30
  text "ANT_TX1" at 1355.15,1755.34 h30
  text "GND" at 1031.11,1752.48 h30
  text "LED" at 2651.97,1752.48 h30
  text "INT" at 2347.37,1745.34 h30
  text "CZ_TX2" at 1355.15,1653.91 h30
  text "VCC_A" at 971.7,1652.48 h30
  text "PWM" at 2646.97,1652.48 h30
  text "TX2" at 514.24,1645.4 h30
  text "GND" at 2325.38,1643.91 h30
  text "-5V" at 831.97,1637.48 h30
  text "RUN" at 2965.97,1637.48 h36
  text "TX2" at 330.97,1577.48 h30 r90
  text "GND" at 1031.11,1552.48 h30
  text "ANT_TX2" at 1355.15,1552.48 h30
  text "U1_TX" at 2281.39,1552.48 h30
  text "U1_RX" at 2641.97,1552.48 h30
  text "8TX" at 514.24,1545.4 h30
  text "VEE_S" at 831.97,1537.48 h30
  text "GND" at 330.97,1468.48 h30 r90
  text "GND" at 3731.97,1462.48 h30
  text "TX1" at 514.24,1440.4 h30
  text "GND" at 836.97,1437.48 h30
  text "NRST" at 3731.97,1362.48 h30
  text "BOOT1" at 3731.97,1262.48 h30
  text "TX2" at 330.97,1195.48 h30 r90
  text "BOOT0" at 3731.97,1162.48 h30
  text "GND" at 330.97,1087.48 h30 r90
  text "3.3V" at 3731.97,1062.48 h30
  text "GND" at 1121.97,997.48 h30
  text "ANT_TX2" at 1226.97,997.48 h30
  text "GND" at 1476.97,997.48 h30
  text "ANT_TX1" at 1581.97,997.48 h30
  text "TX1" at 330.97,996.48 h30 r90
  text "INT" at 1981.97,992.48 h30
  text "NRST" at 2066.97,992.48 h30
  text "GND" at 2191.97,992.48 h30
  text "ANT5" at 500.24,765.4 h30
  text "ANT6" at 860.24,765.4 h30
  text "ANT7" at 1205.24,765.4 h30
  text "ANT8" at 1555.24,765.4 h30
  text "3V3" at 1935.24,759.4 h30
  text "SCL" at 2040.24,759.4 h30
  text "SDA" at 2135.24,759.4 h30
  text "GND" at 2240.24,759.4 h30
  text "I2C" at 2431.97,587.48 h65 r90
  text "ANT1" at 506.24,462.4 h30
  text "ANT2" at 861.24,462.4 h30
  text "ANT3" at 1211.24,462.4 h30
  text "ANT4" at 1561.24,462.4 h30
  text "RST" at 2826.97,462.48 h65
  text "3V3" at 1921.97,460.48 h30
  text "TXD1" at 2017.97,460.48 h30
  text "RXD1" at 2131.97,460.48 h30
  text "GND" at 2247.97,460.48 h30
  text "UART1" at 2451,235 h65 r90
  text "BEEP" at 3496,182 h65
Mechanical 1:
  lines w5: -193.03,157.48 -58.03,157.48 -83.03,132.48 ; -0.07,3257.45 cw(c49.57,3257.45) 49.14,3307.08 ; -0.04,207.04 -0.04,3257.45 ; 0,207.54 ccw(c50,207.54) 49.56,157.54 49.56,78.74 0,78.74 0,0 3936.97,0 3936.97,78.74 3886.97,78.74 3886.97,157.48 ccw(c3886.97,207.48) 3936.97,207.04 3936.97,3257.54 ccw(c3887.46,3257.54) 3887.89,3307.04 ; 49.46,157.54 3886.97,157.54 ; 49.57,3307.09 3887.89,3307.09
  text "VCUT" at -188.03,182.48 h36
Mechanical 2:
  drawing of 637 lines, arcs and shapes, not listed
  text "PCB加工工艺要求" at 6111.97,4292.48 h280
  text "mm x" at 5308.97,4106.48 h100
  text "mm" at 5918.97,4106.48 h100
  text "100" at 4973.97,4097.48 h100
  text "84" at 5583.97,4097.48 h100
  text "IPC-600E   IPC-6011/12" at 7076.97,4096.48 h100
  text "IPC-Ⅱ" at 8411.97,4095.48 h100
  text "IPC-Ⅲ" at 8911.97,4095.48 h100
  text "尺寸" at 4420.67,4078.62 h150
  text "验收标准" at 6420.67,4078.62 h150
  text "FR4 TG140" at 5126.97,3896.48 h100
  text "FR4 TG170" at 6026.97,3896.48 h100
  text "生益有胶材料" at 6926.97,3896.48 h100
  text "MEGTRON6" at 7826.97,3896.48 h100
  text "其他：" at 8726.97,3896.48 h100
  text "板材" at 4419.24,3878.41 h150
  text "单面" at 5126.97,3696.48 h100
  text "2" at 5826.97,3696.48 h100
  text "4" at 6526.97,3696.48 h100
  text "6" at 7226.97,3696.48 h100
  text "8" at 7926.97,3696.48 h100
  text "10" at 8626.97,3696.48 h100
  text "板层" at 4419.24,3678.19 h150
  text "0.4mm" at 5126.97,3496.48 h100
  text "0.6mm" at 5676.97,3496.48 h100
  text "0.8mm" at 6226.97,3496.48 h100
  text "1.0mm" at 6776.97,3496.48 h100
  text "1.2mm" at 7326.97,3496.48 h100
  text "1.4mm" at 7876.97,3496.48 h100
  text "1.6mm" at 8426.97,3496.48 h100
  text "1.8mm" at 8976.97,3496.48 h100
  text "2.0mm" at 9526.97,3496.48 h100
  text "板厚" at 4419.24,3477.98 h150
  text "1/2OZ" at 6356.97,3296.48 h100
  text "1OZ" at 6856.97,3296.48 h100
  text "2OZ" at 7356.97,3296.48 h100
  text "（完成铜厚）" at 5360.27,3283.73 h130
  text "外层" at 5084.02,3277.48 h150
  text "铜厚" at 4419.1,3276.19 h150
  text "白色" at 5576.97,3096.48 h100
  text "其他：" at 6276.97,3096.48 h100
  text "丝印颜色" at 4419.1,3076.98 h150
  text "绿色" at 5576.97,2896.48 h100
  text "黑色" at 6276.97,2896.48 h100
  text "红色" at 6976.97,2896.48 h100
  text "蓝色" at 7676.97,2896.48 h100
  text "黄色" at 8376.97,2896.48 h100
  text "其他：" at 9076.97,2896.48 h100
  text "（亮光）" at 4959.47,2883.88 h130
  text "阻焊颜色" at 4419.1,2876.77 h150
  text "沉镍金" at 5576.97,2696.48 h100
  text "无铅喷锡" at 6276.97,2696.48 h100
  text "电镀镍金" at 6976.97,2696.48 h100
  text "电镀软金" at 7676.97,2696.48 h100
  text "化学沉锡" at 8376.97,2696.48 h100
  text "光板" at 9076.97,2696.48 h100
  text "OSP" at 9596.97,2696.48 h100
  text "表面处理工艺" at 4419.1,2675.55 h150
  text "无" at 5576.97,2497.48 h100
  text "按键镀硬金" at 5996.97,2497.48 h100
  text "金手指" at 6716.97,2497.48 h100
  text "半孔工艺" at 7406.97,2497.48 h100
  text "FPCB补强" at 8096.97,2497.48 h100
  text "树脂塞孔" at 8786.97,2497.48 h100
  text "电镀填孔" at 9476.97,2497.48 h100
  text "特殊工艺" at 4419.1,2476.34 h150
  text "是，但双面开窗除外" at 5576.97,2296.48 h100
  text "否" at 6721.97,2296.48 h100
  text "按文件" at 7421.97,2296.48 h100
  text "是否阻焊塞孔" at 4419.24,2275.69 h150
  text "非拼板" at 5576.97,2096.48 h100
  text "拼板" at 6276.97,2096.48 h100
  text "分成单板交货" at 6976.97,2096.48 h100
  text "交货方式" at 4419.1,2076.48 h150
  text "Gerber输出：英制、相对零点、抑制前导零、精度2:5" at 4421.97,1902.48 h120
  text "Ver 19.01.16" at 9116.97,1835.48 h120
  text "NC Drill输出：英制、相对零点、抑制前导零、精度2:4" at 4421.97,1762.48 h120
  text "R" at 9467.97,1632.98 h25
  text "其他说明" at 4416.97,1587.48 h150
  text "94V-0" at 9537.97,1577.48 h46
  text "标识样式>>>" at 8676.97,1522.48 h120
  text "CTI>=175" at 9381.97,1492.48 h86.61
  text "1." at 4391.97,1452.48 h120
  text "机械1层(*.GM1)为外形铣边；若存在工艺副边，请在副边上增加分流点" at 4516.97,1452.48 h120
  text "2." at 4391.86,1322.48 h120
  text "请用供应商UL认证号，防火等级，CTI等级，生产周期替换放置在板上的UR标识，且保持其位置、方向一致；" at 4516.97,1322.48 h120
  text "禁止添加板内不存在的标识，包括供应商LOGO、无铅等。但工艺副边不受限" at 4516.97,1192.48 h120
  text "3." at 4391.97,1062.48 h120
  text "若焊盘开窗与丝印油冲突，焊盘处需将丝印油掏开，不允许上盘" at 4516.97,1062.48 h120
  text "4." at 4391.97,942.48 h120
  text "若存在V-CUT，无特别说明时，须为双面V-CUT，角度30（+-5°），余量按以下表格执行" at 4516.97,942.48 h120
  text "PCB厚度（mm）" at 4947.97,767.48 h120
  text "筋厚" at 4612.97,752.48 h120
  text "（余量）" at 4562.97,632.48 h120
  text "0.6" at 4947.97,627.48 h120
  text "0.8" at 5187.6,627.48 h120
  text "1" at 5483.9,627.48 h120
  text "1.2" at 5667.97,627.48 h120
  text "1.6" at 5907.97,627.48 h120
  text "2" at 6192.97,627.48 h120
  text "2.5" at 6387.37,627.48 h120
  text "3" at 6672.97,627.48 h120
  text "0.16" at 4918.11,489.98 h120
  text "0.2" at 5188.11,489.98 h120
  text "0.3" at 5428.11,489.98 h120
  text "0.3" at 5663.98,489.98 h120
  text "0.4" at 5904.49,489.98 h120
  text "0.5" at 6148.26,489.98 h120
  text "0.5" at 6388.11,489.98 h120
  text "最小值" at 4557.97,487.48 h120
  text "0.5" at 6626.97,487.48 h120
  text "0.32" at 4918.51,352.48 h120
  text "0.4" at 5187.82,352.48 h120
  text "0.45" at 5397.96,352.48 h120
  text "0.5" at 5663.69,352.48 h120
  text "0.6" at 5906.97,352.48 h120
  text "0.7" at 6148.55,352.48 h120
  text "0.8" at 6388.28,352.48 h120
  text "0.8" at 6628.09,352.48 h120
  text "最大值" at 4557.97,347.48 h120
  text "5." at 4391.97,177.48 h120
  text "PCB做完后，请高温烘烤进行应力释放，再整平（或重物压板烘烤），防止翘曲" at 4516.97,177.48 h120
  text "我司生产使用无铅工艺制程" at 4511.97,42.48 h120
  text "6." at 4391.97,37.48 h120
  text "7." at 4391.97,-107.52 h120
  text "未尽事项请参照我司《PCB质量补充协议》" at 4511.97,-107.52 h120
Mechanical 15:
  lines w5: -39.41,3110.24 3936.97,3110.24 ; -0.04,354.33 3936.97,354.33 ; -0.04,3257.48 -0.04,3307.09 49.96,3307.09 ; 3886.97,157.48 3936.97,157.48 3936.97,212.54
Drill Drawing:
  text ".Legend" at 36.97,3527.48 h36

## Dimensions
3936.97,-65.55 to 0,-65.55 on Mechanical 1
4002.52,3307.09 to 4002.52,0 on Mechanical 1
